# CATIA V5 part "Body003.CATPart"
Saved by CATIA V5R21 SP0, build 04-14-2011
Part number: Body003
Definition: design
Nomenclature: Body003
Source: Unknown
Bounding box of the stored display mesh (mm): x -2.2 to 2.2, y -2.22 to 2.22, z 0 to 1
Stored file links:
  C:\Users\beatr\OneDrive\Documents\UNB\2026_1\Pi1\Componentes eletronicos\Encoder\Body003.CATPart
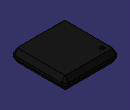
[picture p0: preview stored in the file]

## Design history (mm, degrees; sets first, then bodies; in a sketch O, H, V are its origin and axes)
Body1 "MANIFOLD_SOLID_BREP #2561" (main body)
  Solid1: solid without history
